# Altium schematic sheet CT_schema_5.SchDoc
size 287 x 163 mm
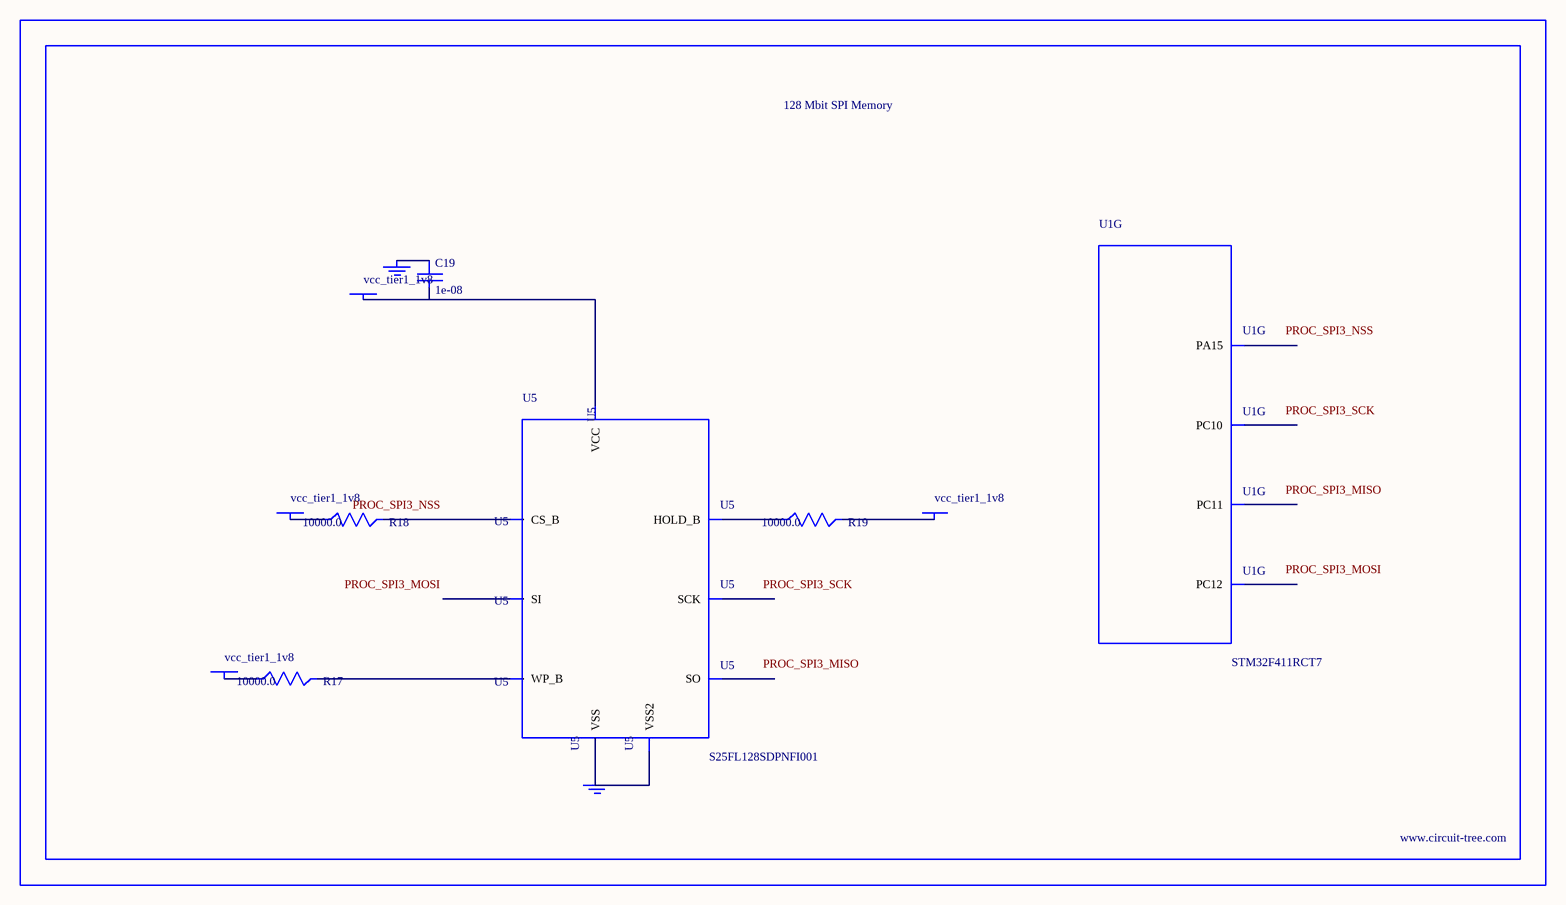
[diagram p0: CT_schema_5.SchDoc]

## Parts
BORDER4  (no value)
C19  1e-08  [C0402]
GND_INSTANCE_4_0  (no value)
GND_INSTANCE_4_1  (no value)
POWER_INSTANCE_4_0  vcc_tier1_1v8
POWER_INSTANCE_4_1  vcc_tier1_1v8
POWER_INSTANCE_4_2  vcc_tier1_1v8
POWER_INSTANCE_4_3  vcc_tier1_1v8
R17  10000.0  [R0603]
R18  10000.0  [R0603]
R19  10000.0  [R0603]
U1  STM32F411RCT7  [LQFP64]  (part G of 8)
U5  S25FL128SDPNFI001  [WNG008]

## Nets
NetC19_1: C19.1 GND_INSTANCE_4_0.0(GND)
NetC19_2: C19.2 POWER_INSTANCE_4_3.0(PWR) U5.8(VCC)
NetGND_INSTANCE_4_1_0: GND_INSTANCE_4_1.0(GND) U5.4(VSS) U5.PAD(VSS2)
NetPOWER_INSTANCE_4_0_0: POWER_INSTANCE_4_0.0(PWR) R18.1
NetPOWER_INSTANCE_4_1_0: POWER_INSTANCE_4_1.0(PWR) R17.1
NetPOWER_INSTANCE_4_2_0: POWER_INSTANCE_4_2.0(PWR) R19.2
NetR17_2: R17.2 U5.3(WP_B)
NetR18_2: R18.2 U5.1(CS_B)
NetR19_1: R19.1 U5.7(HOLD_B)

Not connected (* = marked no-connect by the designer): U1 50(PA15) 51(PC10) 52(PC11) 53(PC12); U5 2(SO) 5(SI) 6(SCK)

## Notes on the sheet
- Labels drawn without touching a wire or pin: PROC_SPI3_MISO, PROC_SPI3_MOSI, PROC_SPI3_NSS, PROC_SPI3_SCK

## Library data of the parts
BORDER4 = BORDER_PAGE4
C19 = C0402C103K3RAC
GND_INSTANCE_4_0 GND_INSTANCE_4_1 = GND
POWER_INSTANCE_4_0-POWER_INSTANCE_4_3 = PWR
R17-R19 = RC0603JR-0710KL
